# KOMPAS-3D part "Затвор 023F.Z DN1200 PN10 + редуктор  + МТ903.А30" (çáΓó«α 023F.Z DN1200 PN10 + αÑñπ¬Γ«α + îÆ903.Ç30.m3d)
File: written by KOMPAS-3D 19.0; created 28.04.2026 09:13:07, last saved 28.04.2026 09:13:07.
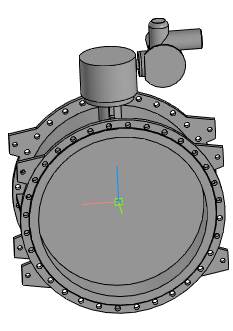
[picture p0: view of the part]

Document properties: Полное имя файла: ..\..\Затвор 023F.Z DN400-DN1600 + редуктор + МТ903\Затвор 023F.Z DN1200 PN10 + редуктор + МТ903.А30.a3d

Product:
- Part/product: Затвор 023F.Z DN1200 PN10 + редуктор  + МТ903.А30
    Масса: 2218.91

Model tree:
1. Операция без истории:1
